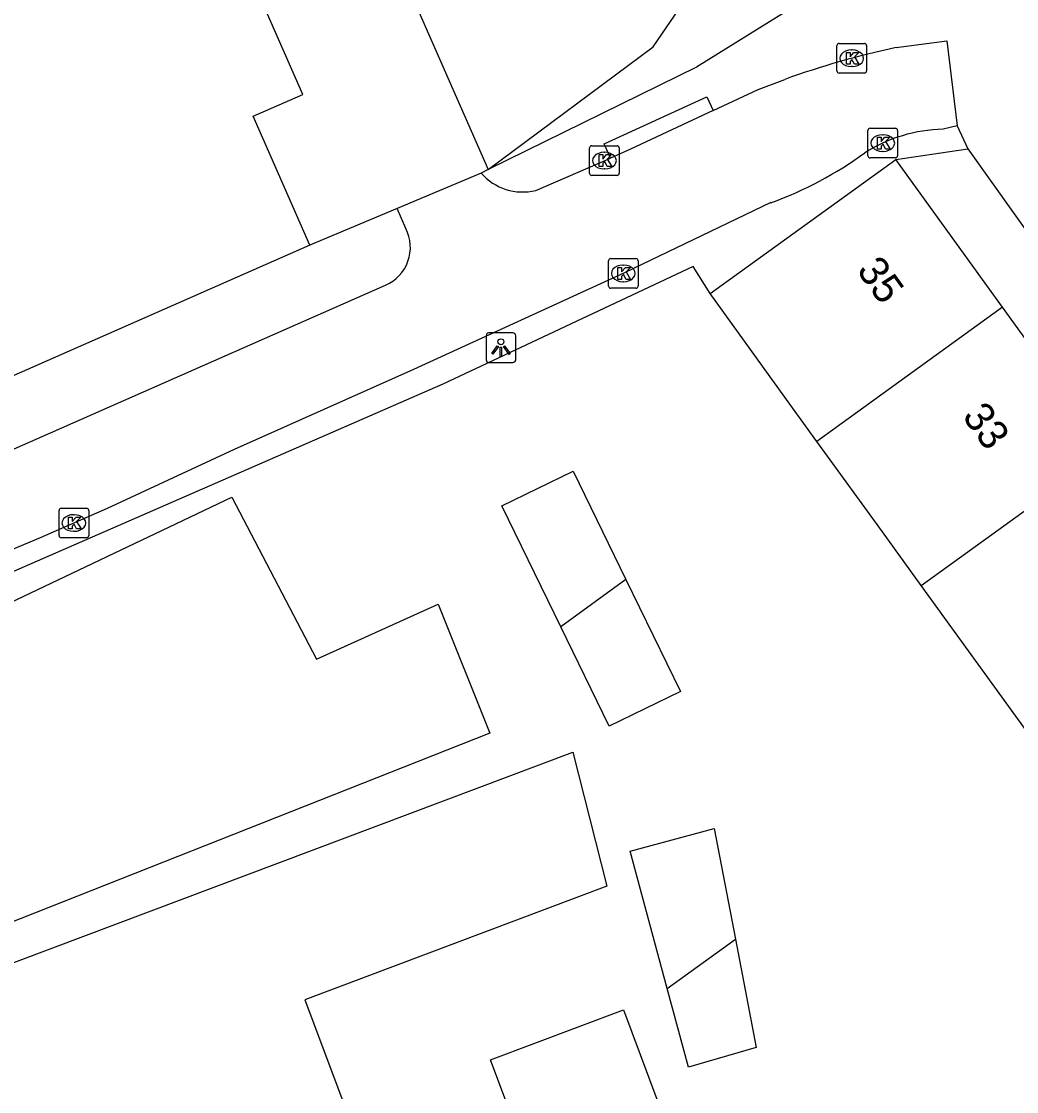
# Model space of a CAD drawing. Extents: x 161882 to 162509, y 381687 to 382379.
# Drawn here: x 162105.57 to 162139.15, y 381980.92 to 382017.01 of the extents above; entities that cross this region are included whole.
import ezdxf

# ---------------------------------------------------------------- set-up
doc = ezdxf.new("R2010")
doc.units = 0
for name, color, linetype in [('IMGEO_Kolk', 7, 'Continuous'), ('IMGEO_Lichtpunt', 7, 'Continuous'), ('IMGEO_Muur', 7, 'Continuous'), ('IMGEO_Pand', 7, 'Continuous'), ('IMGEO_Pand_nummerreeks', 7, 'Continuous'), ('IMGEO_Pand_vergunning_verleend', 7, 'Continuous'), ('IMGEO_Rijbaan_lokaal_open', 7, 'Continuous'), ('IMGEO_Voetpad_open', 7, 'Continuous'), ('IMGEO_Woonerf_open', 7, 'Continuous')]:
    doc.layers.add(name, color=color, linetype=linetype)

msp = doc.modelspace()

# ---------------------------------------------------------------- linework, layer by layer
at = {"layer": 'IMGEO_Kolk'}
for p, q in [((162133.091, 382015.342), (162133.091, 382016.194)), ((162133.166, 382016.268), (162134.018, 382016.268)), ((162134.092, 382016.194), (162134.092, 382015.342)), ((162133.579, 382016.048), (162133.604, 382016.048)), ((162133.602, 382015.488), (162133.577, 382015.488)), ((162134.018, 382015.268), (162133.166, 382015.268)), ((162134.139, 382012.482), (162134.139, 382013.334)), ((162134.214, 382013.408), (162135.066, 382013.408)), ((162134.627, 382013.188), (162134.652, 382013.188)), ((162135.14, 382013.334), (162135.14, 382012.482)), ((162124.822, 382012.818), (162125.674, 382012.818)), ((162124.747, 382011.892), (162124.747, 382012.744)), ((162125.235, 382012.598), (162125.26, 382012.598)), ((162125.748, 382012.744), (162125.748, 382011.892)), ((162134.65, 382012.628), (162134.625, 382012.628)), ((162135.066, 382012.408), (162134.214, 382012.408)), ((162125.674, 382011.818), (162124.822, 382011.818)), ((162125.258, 382012.038), (162125.233, 382012.038)), ((162125.383, 382008.086), (162125.383, 382008.938)), ((162125.458, 382009.012), (162126.31, 382009.012)), ((162126.384, 382008.938), (162126.384, 382008.086)), ((162125.871, 382008.792), (162125.896, 382008.792)), ((162125.894, 382008.232), (162125.869, 382008.232)), ((162126.31, 382008.012), (162125.458, 382008.012)), ((162106.918, 382000.595), (162107.77, 382000.595)), ((162106.843, 381999.669), (162106.843, 382000.521)), ((162107.331, 382000.375), (162107.356, 382000.375)), ((162107.844, 382000.521), (162107.844, 381999.669)), ((162107.354, 381999.815), (162107.329, 381999.815)), ((162107.77, 381999.595), (162106.918, 381999.595))]:
    msp.add_line(p, q, dxfattribs=at)
for points in [[(162133.091, 382015.342), (162133.091, 382016.194)], [(162133.166, 382016.268), (162134.018, 382016.268)], [(162134.092, 382016.194), (162134.092, 382015.342)], [(162133.412, 382015.968), (162133.535, 382015.968), (162133.535, 382015.817), (162133.665, 382015.968), (162133.829, 382015.968), (162133.683, 382015.817), (162133.836, 382015.568), (162133.684, 382015.568), (162133.599, 382015.732), (162133.535, 382015.665), (162133.535, 382015.568), (162133.412, 382015.568), (162133.412, 382015.968)], [(162134.018, 382015.268), (162133.166, 382015.268)], [(162134.139, 382012.482), (162134.139, 382013.334)], [(162134.214, 382013.408), (162135.066, 382013.408)], [(162135.14, 382013.334), (162135.14, 382012.482)], [(162124.822, 382012.818), (162125.674, 382012.818)], [(162134.46, 382013.108), (162134.583, 382013.108), (162134.583, 382012.957), (162134.713, 382013.108), (162134.877, 382013.108), (162134.731, 382012.957), (162134.884, 382012.708), (162134.732, 382012.708), (162134.647, 382012.872), (162134.583, 382012.805), (162134.583, 382012.708), (162134.46, 382012.708), (162134.46, 382013.108)], [(162124.747, 382011.892), (162124.747, 382012.744)], [(162125.068, 382012.518), (162125.191, 382012.518), (162125.191, 382012.367), (162125.321, 382012.518), (162125.485, 382012.518), (162125.339, 382012.367), (162125.492, 382012.118), (162125.34, 382012.118), (162125.255, 382012.282), (162125.191, 382012.215), (162125.191, 382012.118), (162125.068, 382012.118), (162125.068, 382012.518)], [(162125.748, 382012.744), (162125.748, 382011.892)], [(162135.066, 382012.408), (162134.214, 382012.408)], [(162125.674, 382011.818), (162124.822, 382011.818)], [(162125.383, 382008.086), (162125.383, 382008.938)], [(162125.458, 382009.012), (162126.31, 382009.012)], [(162126.384, 382008.938), (162126.384, 382008.086)], [(162125.704, 382008.712), (162125.827, 382008.712), (162125.827, 382008.561), (162125.957, 382008.712), (162126.121, 382008.712), (162125.975, 382008.561), (162126.128, 382008.312), (162125.976, 382008.312), (162125.891, 382008.476), (162125.827, 382008.409), (162125.827, 382008.312), (162125.704, 382008.312), (162125.704, 382008.712)], [(162126.31, 382008.012), (162125.458, 382008.012)], [(162106.918, 382000.595), (162107.77, 382000.595)], [(162106.843, 381999.669), (162106.843, 382000.521)], [(162107.164, 382000.295), (162107.287, 382000.295), (162107.287, 382000.144), (162107.417, 382000.295), (162107.581, 382000.295), (162107.435, 382000.144), (162107.588, 381999.895), (162107.436, 381999.895), (162107.351, 382000.059), (162107.287, 381999.992), (162107.287, 381999.895), (162107.164, 381999.895), (162107.164, 382000.295)], [(162107.844, 382000.521), (162107.844, 381999.669)], [(162107.77, 381999.595), (162106.918, 381999.595)]]:
    msp.add_lwpolyline(points, dxfattribs=at)
for centre, start, end in [((162133.168, 382016.192), 91.552, 178.448), ((162133.168, 382016.192), 91.552, 178.448), ((162134.016, 382016.192), 1.552, 88.448), ((162134.016, 382016.192), 1.552, 88.448), ((162133.168, 382015.344), 181.552, 268.448), ((162133.168, 382015.344), 181.552, 268.448), ((162134.016, 382015.344), 271.552, 358.448), ((162134.016, 382015.344), 271.552, 358.448), ((162134.216, 382013.332), 91.552, 178.448), ((162134.216, 382013.332), 91.552, 178.448), ((162135.064, 382013.332), 1.552, 88.448), ((162135.064, 382013.332), 1.552, 88.448), ((162124.824, 382012.742), 91.552, 178.448), ((162124.824, 382012.742), 91.552, 178.448), ((162125.672, 382012.742), 1.552, 88.448), ((162125.672, 382012.742), 1.552, 88.448), ((162134.216, 382012.484), 181.552, 268.448), ((162134.216, 382012.484), 181.552, 268.448), ((162135.064, 382012.484), 271.552, 358.448), ((162135.064, 382012.484), 271.552, 358.448), ((162124.824, 382011.894), 181.552, 268.448), ((162124.824, 382011.894), 181.552, 268.448), ((162125.672, 382011.894), 271.552, 358.448), ((162125.672, 382011.894), 271.552, 358.448), ((162125.46, 382008.936), 91.552, 178.448), ((162125.46, 382008.936), 91.552, 178.448), ((162126.308, 382008.936), 1.552, 88.448), ((162126.308, 382008.936), 1.552, 88.448), ((162125.46, 382008.088), 181.552, 268.448), ((162125.46, 382008.088), 181.552, 268.448), ((162126.308, 382008.088), 271.552, 358.448), ((162126.308, 382008.088), 271.552, 358.448), ((162106.92, 382000.519), 91.552, 178.448), ((162106.92, 382000.519), 91.552, 178.448), ((162107.768, 382000.519), 1.552, 88.448), ((162107.768, 382000.519), 1.552, 88.448), ((162106.92, 381999.671), 181.552, 268.448), ((162106.92, 381999.671), 181.552, 268.448), ((162107.768, 381999.671), 271.552, 358.448), ((162107.768, 381999.671), 271.552, 358.448)]:
    msp.add_arc(centre, 0.0765, start, end, dxfattribs=at)
for centre, major_axis, ratio, start_param, end_param in [((162133.578, 382015.768), (-0.387, 0.002), 0.722429, 4.712389, 7.853982), ((162133.603, 382015.768), (-0.39, 0.002), 0.717154, 1.570796, 4.712389), ((162134.626, 382012.908), (-0.387, 0.002), 0.722429, 4.712389, 7.853982), ((162134.651, 382012.908), (-0.39, 0.002), 0.717154, 1.570796, 4.712389), ((162125.234, 382012.318), (-0.387, 0.002), 0.722429, 4.712389, 7.853982), ((162125.259, 382012.318), (-0.39, 0.002), 0.717154, 1.570796, 4.712389), ((162125.87, 382008.512), (-0.387, 0.002), 0.722429, 4.712389, 7.853982), ((162125.895, 382008.512), (-0.39, 0.002), 0.717154, 1.570796, 4.712389), ((162107.33, 382000.095), (-0.387, 0.002), 0.722429, 4.712389, 7.853982), ((162107.355, 382000.095), (-0.39, 0.002), 0.717154, 1.570796, 4.712389)]:
    msp.add_ellipse(centre, major_axis=major_axis, ratio=ratio, start_param=start_param, end_param=end_param, dxfattribs=at)
at = {"layer": 'IMGEO_Lichtpunt'}
for p, q in [((162121.256, 382006.41), (162121.256, 382005.603)), ((162121.256, 382006.41), (162121.256, 382005.603)), ((162122.158, 382006.505), (162121.35, 382006.505)), ((162122.158, 382006.505), (162121.35, 382006.505)), ((162122.252, 382005.603), (162122.252, 382006.41)), ((162122.252, 382005.603), (162122.252, 382006.41)), ((162121.35, 382005.509), (162122.158, 382005.509)), ((162121.35, 382005.509), (162122.158, 382005.509))]:
    msp.add_line(p, q, dxfattribs=at)
for points in [[(162121.63, 382006.074), (162121.669, 382006.046), (162121.481, 382005.784), (162121.443, 382005.811), (162121.63, 382006.074)], [(162121.732, 382006.026), (162121.779, 382006.026), (162121.779, 382005.704), (162121.732, 382005.704), (162121.732, 382006.026)], [(162121.842, 382006.046), (162121.88, 382006.073), (162122.067, 382005.811), (162122.028, 382005.783), (162121.842, 382006.046)]]:
    msp.add_lwpolyline(points, dxfattribs=at)
msp.add_circle((162121.755, 382006.208), 0.0994, dxfattribs=at)
for centre, start, end in [((162121.35, 382006.41), 90, 180), ((162121.35, 382006.41), 90, 180), ((162122.158, 382006.41), 0, 90), ((162122.158, 382006.41), 0, 90), ((162121.35, 382005.603), 180, 270), ((162121.35, 382005.603), 180, 270), ((162122.158, 382005.603), 270, 0), ((162122.158, 382005.603), 270, 360)]:
    msp.add_arc(centre, 0.0946, start, end, dxfattribs=at)
at = {"layer": 'IMGEO_Muur'}
msp.add_lwpolyline([(162128.814, 382007.832), (162128.245, 382008.75), (162119.792, 382004.774)], dxfattribs=at)
at = {"layer": 'IMGEO_Pand'}
for points in [[(162123.943, 382025.832), (162120.71, 382021.064), (162118.724, 382022.411), (162117.529, 382020.65), (162119.313, 382016.593), (162121.326, 382012.016)], [(162115.312, 382009.466), (162113.399, 382013.814), (162115.076, 382014.551), (162113.062, 382019.128), (162111.955, 382021.645), (162110.278, 382020.908), (162108.51, 382024.928)], [(162121.326, 382012.016), (162126.891, 382016.153), (162130.475, 382021.4)], [(162128.814, 382007.832), (162135.074, 382012.356)], [(162138.679, 382007.373), (162135.074, 382012.356)], [(162115.312, 382009.466), (162093.793, 382000), (162085.897, 381996.336)], [(162132.419, 382002.847), (162131.743, 382003.78), (162128.814, 382007.832)], [(162138.679, 382007.373), (162132.419, 382002.847)], [(162142.196, 382002.512), (162138.679, 382007.373)], [(162135.939, 381997.989), (162134.482, 382000), (162132.419, 382002.847)], [(162135.939, 381997.989), (162138.721, 382000), (162142.196, 382002.512)], [(162123.774, 381996.597), (162121.79, 382000.672), (162124.191, 382001.841), (162125.972, 381998.186)], [(162125.972, 381998.186), (162127.81, 381994.412), (162125.408, 381993.242), (162123.774, 381996.597)], [(162125.972, 381998.186), (162123.774, 381996.597)], [(162139.459, 381993.132), (162135.939, 381997.989)], [(162094.493, 381981.199), (162124.179, 381992.364), (162125.323, 381987.847), (162115.138, 381984.016), (162116.818, 381979.55), (162112.686, 381977.996), (162105.938, 381975.458), (162106.111, 381975.02)], [(162127.369, 381984.391), (162126.111, 381989.03), (162128.955, 381989.793), (162129.671, 381986.056)], [(162129.671, 381986.056), (162130.37, 381982.407), (162128.086, 381981.748), (162127.369, 381984.391)], [(162127.369, 381984.391), (162129.671, 381986.056)], [(162122.531, 381978.989), (162121.401, 381981.991), (162125.885, 381983.677), (162127.02, 381980.66)]]:
    msp.add_lwpolyline(points, dxfattribs=at)
at = {"layer": 'IMGEO_Pand_vergunning_verleend'}
msp.add_lwpolyline([(162092.271, 381991.269), (162112.67, 382000.971), (162115.53, 381995.498), (162119.635, 381997.363), (162121.376, 381993.01), (162101.226, 381985.05), (162099.983, 381988.159), (162097.619, 381987.413), (162096.749, 381989.03), (162093.888, 381987.91), (162092.271, 381991.269)], dxfattribs=at)
at = {"layer": 'IMGEO_Rijbaan_lokaal_open'}
for points in [[(162135.09, 382016.129), (162136.8, 382016.356), (162137.154, 382013.486)], [(162128.918, 382014.008), (162130.43, 382014.718), (162131.33, 382015.057)], [(162128.918, 382014.008), (162126.129, 382012.698), (162125.45, 382012.404)], [(162137.154, 382013.486), (162136.674, 382013.377)], [(162122.928, 382011.314), (162125.45, 382012.404)], [(162121.086, 382011.898), (162118.257, 382010.706)], [(162130.863, 382010.899), (162125.921, 382008.53), (162118.799, 382005.274), (162112.758, 382002.577), (162108.469, 382000.584), (162106.212, 381999.596), (162100.046, 381997.014), (162092.114, 381993.53)], [(162118.549, 382010.023), (162118.257, 382010.706)], [(162087.193, 381994.544), (162098.981, 381999.805), (162099.424, 382000), (162117.865, 382008.115)]]:
    msp.add_lwpolyline(points, dxfattribs=at)
for centre, radius, start, end in [((162141.081, 381987.984), 28.775, 102.0177, 109.8087), ((162136.796, 382008.19), 5.188, 91.3507, 122.1672), ((162126.607, 382022.747), 12.59, 289.7601, 306.154), ((162122.481, 382013.1), 1.841, 220.7565, 284.0614), ((162117.305, 382009.392), 1.395, 293.6742, 26.8813)]:
    msp.add_arc(centre, radius, start, end, dxfattribs=at)
at = {"layer": 'IMGEO_Voetpad_open'}
for points in [[(162125.45, 382012.404), (162125.233, 382012.879), (162128.706, 382014.471), (162128.918, 382014.008)], [(162137.154, 382013.486), (162137.504, 382012.714)], [(162135.074, 382012.356), (162137.504, 382012.714)], [(162118.257, 382010.706), (162115.312, 382009.466)], [(162128.814, 382007.832), (162128.245, 382008.75), (162119.792, 382004.774), (162088.878, 381991.295)]]:
    msp.add_lwpolyline(points, dxfattribs=at)
at = {"layer": 'IMGEO_Woonerf_open'}
for points in [[(162138.544, 382023.007), (162136.45, 382021.204), (162131.472, 382017.407), (162128.348, 382015.464), (162121.326, 382012.016)], [(162137.504, 382012.714), (162144.573, 382002.81)], [(162121.326, 382012.016), (162121.086, 382011.898)]]:
    msp.add_lwpolyline(points, dxfattribs=at)

# ---------------------------------------------------------------- texts
at = {"layer": 'IMGEO_Pand_nummerreeks'}
for s, p in [('35', (162133.735, 382008.611)), ('33', (162137.296, 382003.689))]:
    msp.add_text(s, height=1, rotation=305.884, dxfattribs=at).set_placement(p)

doc.saveas('drawing.dxf')
